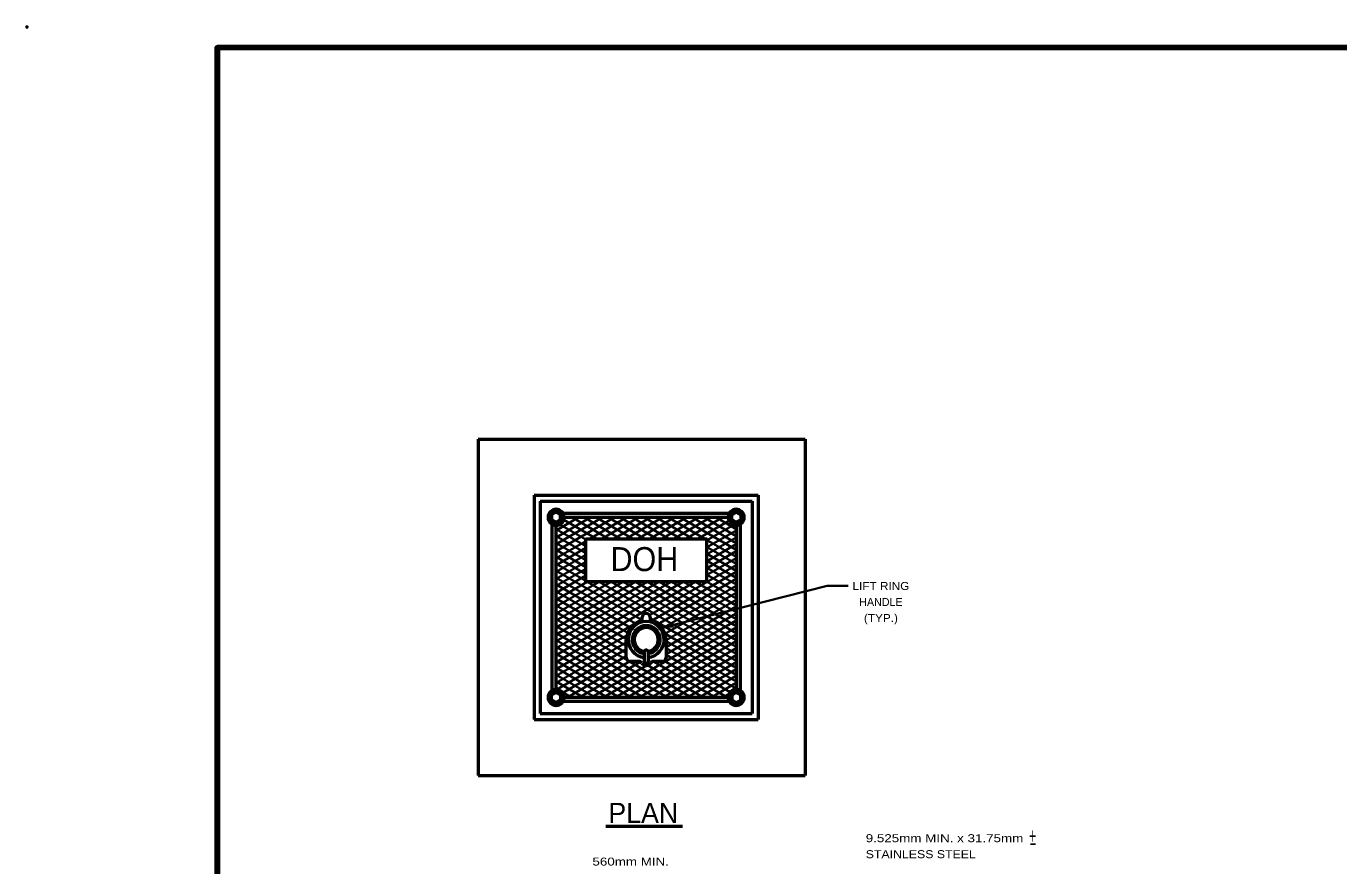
# Model space of a CAD drawing. Extents: x 442 to 1297, y -1132 to -588.
# Drawn here: x 441.8 to 835.5, y -839.5 to -587.7 of the extents above; entities that cross this region are included whole.
import ezdxf
from ezdxf.enums import TextEntityAlignment as Align

# ---------------------------------------------------------------- set-up
doc = ezdxf.new("R2010")
doc.units = 0
doc.header["$LTSCALE"] = 0.96
doc.header["$PDMODE"] = 32
doc.header["$PDSIZE"] = 0.48
doc.layers.add('1', color=7, linetype='Continuous', lineweight=35)

msp = doc.modelspace()

# ---------------------------------------------------------------- linework, layer by layer
at = {"layer": '1', "lineweight": 53}
for p, q in [((577.3476, -711.5929), (577.3476, -812.3929)), ((577.3476, -711.5929), (675.4476, -711.5929)), ((675.4476, -711.5929), (675.4476, -812.3929)), ((594.1476, -728.3929), (661.3476, -728.3929)), ((594.1476, -728.3929), (594.1476, -795.5929)), ((595.9476, -730.1929), (659.5476, -730.1929)), ((595.9476, -730.1929), (595.9476, -793.7929)), ((659.5476, -730.1929), (659.5476, -793.7929)), ((661.3476, -728.3929), (661.3476, -795.5929)), ((602.8261, -733.7929), (652.6691, -733.7929)), ((603.1476, -734.9929), (652.3476, -734.9929)), ((599.5476, -786.9144), (599.5476, -737.0714)), ((600.7476, -786.5929), (600.7476, -737.3929)), ((654.7476, -737.3929), (654.7476, -786.5929)), ((655.9476, -737.0714), (655.9476, -786.9144)), ((626.5476, -765.7284), (626.5476, -764.9459)), ((628.9476, -764.9459), (628.9476, -765.7284)), ((621.7926, -777.0434), (621.7926, -771.8587)), ((627.1497, -775.3059), (627.1497, -778.2434)), ((628.3455, -775.3059), (628.3455, -778.2434)), ((633.7029, -771.8012), (633.7029, -777.0434)), ((625.511, -778.2434), (622.9926, -778.2434)), ((632.5029, -778.2434), (629.9842, -778.2434)), ((652.3476, -790.1929), (602.8261, -790.1929)), ((652.3476, -788.9929), (603.1476, -788.9929)), ((595.9476, -793.7929), (659.5476, -793.7929)), ((594.1476, -795.5929), (661.3476, -795.5929)), ((577.3476, -812.3929), (675.4476, -812.3929)), ((615.6693, -827.601), (638.6356, -827.601))]:
    msp.add_line(p, q, dxfattribs=at)
at = {"layer": '1'}
for p, q in [((600.7476, -738.9178), (607.5458, -734.9929)), ((600.7476, -740.9963), (611.1458, -734.9929)), ((600.7476, -743.0748), (614.7458, -734.9929)), ((600.7476, -745.1532), (618.3458, -734.9929)), ((612.8985, -741.3983), (603.0297, -735.7005)), ((603.0762, -735.4949), (603.9458, -734.9929)), ((616.4985, -741.3983), (605.404, -734.9929)), ((620.0985, -741.3983), (609.004, -734.9929)), ((610.8513, -741.3983), (621.9458, -734.9929)), ((623.6985, -741.3983), (612.604, -734.9929)), ((614.4513, -741.3983), (625.5458, -734.9929)), ((627.2985, -741.3983), (616.204, -734.9929)), ((618.0513, -741.3983), (629.1458, -734.9929)), ((630.8985, -741.3983), (619.804, -734.9929)), ((621.6513, -741.3983), (632.7458, -734.9929)), ((634.4985, -741.3983), (623.404, -734.9929)), ((625.2513, -741.3983), (636.3458, -734.9929)), ((638.0985, -741.3983), (627.004, -734.9929)), ((628.8513, -741.3983), (639.9458, -734.9929)), ((641.6985, -741.3983), (630.604, -734.9929)), ((632.4513, -741.3983), (643.5458, -734.9929)), ((645.2985, -741.3983), (634.204, -734.9929)), ((636.0513, -741.3983), (647.1458, -734.9929)), ((654.7476, -744.7753), (637.804, -734.9929)), ((639.6513, -741.3983), (650.7458, -734.9929)), ((654.7476, -742.6968), (641.404, -734.9929)), ((643.2513, -741.3983), (652.5867, -736.0085)), ((654.7476, -740.6184), (645.004, -734.9929)), ((654.7476, -738.5399), (648.604, -734.9929)), ((652.358, -735.0818), (652.204, -734.9929)), ((609.6447, -743.6766), (600.7476, -738.5399)), ((609.6447, -741.5982), (601.8739, -737.1117)), ((645.8505, -741.9761), (654.0056, -737.2678)), ((645.8505, -744.0546), (654.7476, -738.9178)), ((609.6447, -745.7551), (600.7476, -740.6184)), ((600.7476, -747.2317), (609.6447, -742.0949)), ((609.6447, -747.8336), (600.7476, -742.6968)), ((645.8505, -746.133), (654.7476, -740.9963)), ((654.7476, -746.8538), (645.8505, -741.717)), ((645.8505, -748.2115), (654.7476, -743.0748)), ((654.7476, -748.9322), (645.8505, -743.7955)), ((600.7476, -749.3101), (609.6447, -744.1734)), ((609.6447, -749.912), (600.7476, -744.7753)), ((600.7476, -751.3886), (609.6447, -746.2519)), ((609.6447, -751.9905), (600.7476, -746.8538)), ((645.8505, -750.29), (654.7476, -745.1532)), ((654.7476, -751.0107), (645.8505, -745.8739)), ((645.8505, -752.3684), (654.7476, -747.2317)), ((654.7476, -753.0891), (645.8505, -747.9524)), ((600.7476, -753.4671), (609.6447, -748.3303)), ((609.6447, -754.069), (600.7476, -748.9322)), ((600.7476, -755.5455), (609.6447, -750.4088)), ((626.4986, -765.878), (600.7476, -751.0107)), ((628.7271, -764.3331), (654.7476, -749.3101)), ((629.322, -766.0681), (654.7476, -751.3886)), ((654.7476, -755.1676), (645.8505, -750.0309)), ((600.7476, -757.624), (609.6447, -752.4872)), ((624.5229, -766.8158), (600.7476, -753.0891)), ((600.7476, -759.7024), (610.0517, -754.3307)), ((600.7476, -761.7809), (613.6517, -754.3307)), ((600.7476, -763.8594), (617.2517, -754.3307)), ((600.7476, -765.9378), (620.8517, -754.3307)), ((600.7476, -768.0163), (624.4517, -754.3307)), ((600.7476, -770.0948), (628.0517, -754.3307)), ((600.7476, -772.1732), (631.6517, -754.3307)), ((600.7476, -774.2517), (635.2517, -754.3307)), ((600.7476, -776.3301), (638.8517, -754.3307)), ((600.7476, -778.4086), (642.4517, -754.3307)), ((623.1179, -768.0831), (600.7476, -755.1676)), ((627.0042, -764.0915), (610.0981, -754.3307)), ((654.7476, -778.0307), (613.6981, -754.3307)), ((654.7476, -775.9522), (617.2981, -754.3307)), ((654.7476, -773.8737), (620.8981, -754.3307)), ((654.7476, -771.7953), (624.4981, -754.3307)), ((654.7476, -769.7168), (628.0981, -754.3307)), ((631.2702, -767.0217), (654.7476, -753.4671)), ((654.7476, -767.6384), (631.6981, -754.3307)), ((632.4364, -768.1296), (682.0302, -755.499)), ((632.5763, -768.3461), (654.7476, -755.5455)), ((654.7476, -765.5599), (635.2981, -754.3307)), ((654.7476, -763.4814), (638.8981, -754.3307)), ((654.7476, -761.403), (642.4981, -754.3307)), ((654.7476, -757.2461), (645.8505, -752.1093)), ((654.7476, -759.3245), (645.8505, -754.1878)), ((688.3381, -755.499), (682.0302, -755.499)), ((622.2169, -769.6414), (600.7476, -757.2461)), ((621.8177, -771.4894), (600.7476, -759.3245)), ((633.3905, -769.9545), (654.7476, -757.624)), ((633.7029, -771.8526), (654.7476, -759.7024)), ((621.7926, -773.5533), (600.7476, -761.403)), ((621.7926, -775.6318), (600.7476, -763.4814)), ((633.7029, -773.9311), (654.7476, -761.7809)), ((622.2154, -777.9543), (600.7476, -765.5599)), ((600.7476, -780.4871), (626.5476, -765.5914)), ((637.7347, -788.9929), (600.7476, -767.6384)), ((614.8151, -788.9929), (654.7476, -765.9378)), ((654.7476, -780.1091), (628.9476, -765.2135)), ((633.7029, -776.0095), (654.7476, -763.8594)), ((634.1347, -788.9929), (600.7476, -769.7168)), ((600.7476, -782.5655), (622.0013, -770.2947)), ((618.4151, -788.9929), (654.7476, -768.0163)), ((622.0151, -788.9929), (654.7476, -770.0948)), ((654.7476, -782.1876), (633.3509, -769.8342)), ((630.5347, -788.9929), (600.7476, -771.7953)), ((600.7476, -784.644), (621.7926, -772.4936)), ((626.9347, -788.9929), (600.7476, -773.8737)), ((600.954, -786.6032), (621.7926, -774.5721)), ((625.6151, -788.9929), (654.7476, -772.1732)), ((629.2151, -788.9929), (654.7476, -774.2517)), ((654.7476, -784.266), (633.7029, -772.1159)), ((654.7476, -786.3445), (633.7029, -774.1943)), ((623.3347, -788.9929), (600.7476, -775.9522)), ((619.7347, -788.9929), (600.7476, -778.0307)), ((602.7227, -787.6606), (621.7926, -776.6506)), ((604.0151, -788.9929), (622.7173, -778.1952)), ((607.6151, -788.9929), (626.0107, -778.3722)), ((611.2151, -788.9929), (627.8655, -779.3798)), ((641.3347, -788.9929), (622.5956, -778.1739)), ((644.9347, -788.9929), (628.181, -779.3201)), ((629.0588, -778.6908), (629.7682, -778.2812)), ((648.5347, -788.9929), (629.9319, -778.2526)), ((632.8151, -788.9929), (654.7476, -776.3301)), ((652.1347, -788.9929), (633.1587, -778.0371)), ((652.9759, -787.4001), (633.7029, -776.2728)), ((636.4151, -788.9929), (654.7476, -778.4086)), ((616.1347, -788.9929), (600.7476, -780.1091)), ((612.5347, -788.9929), (600.7476, -782.1876)), ((640.0151, -788.9929), (654.7476, -780.4871)), ((643.6151, -788.9929), (654.7476, -782.5655)), ((608.9347, -788.9929), (600.7476, -784.266)), ((601.3349, -786.6836), (600.7476, -786.3445)), ((605.3347, -788.9929), (602.4899, -787.3504)), ((647.2151, -788.9929), (654.7476, -784.644)), ((650.8151, -788.9929), (652.5993, -787.9628))]:
    msp.add_line(p, q, dxfattribs=at)
at = {"layer": '1', "lineweight": 158}
msp.add_lwpolyline([(1290.7447, -594.0679), (499.0447, -594.1679), (499.1447, -1120.1679)], dxfattribs=at)
at = {"layer": '1', "lineweight": 53}
for points in [[(600.7476, -733.4929), (599.3968, -734.2411), (599.3968, -735.7411), (600.7476, -736.4929), (602.0968, -735.7411), (602.0969, -734.2411)], [(654.7476, -733.4929), (656.0984, -734.2411), (656.0984, -735.7411), (654.7476, -736.4929), (653.3984, -735.7411), (653.3983, -734.2411)], [(609.6447, -741.3983), (645.8505, -741.3983), (645.8505, -754.3307), (609.6447, -754.3307)], [(600.7476, -790.4929), (599.3968, -789.7447), (599.3968, -788.2447), (600.7476, -787.4929), (602.0968, -788.2447), (602.0969, -789.7447)], [(654.7476, -790.4929), (656.0984, -789.7447), (656.0984, -788.2447), (654.7476, -787.4929), (653.3984, -788.2447), (653.3983, -789.7447)]]:
    msp.add_lwpolyline(points, close=True, dxfattribs=at)
for centre in [(600.7476, -734.9929), (654.7476, -734.9929), (600.7476, -788.9929), (654.7476, -788.9929)]:
    msp.add_circle(centre, 1.8, dxfattribs=at)
for centre, radius, start, end in [((600.7476, -734.9929), 2.4, 0, 270), ((600.7476, -734.9929), 2.4, 270, 0), ((654.7476, -734.9929), 2.4, 270, 180), ((654.7476, -734.9929), 2.4, 180.14666, 268.87468), ((627.7476, -771.8012), 5.9553, 103.87448, 180.55336), ((627.7606, -771.6704), 5.4, 276.21818, 263.50424), ((627.7606, -771.6704), 4.2, 278.00514, 261.63652), ((626.2476, -765.7284), 0.3, 283.87448, 0), ((627.7476, -765.0136), 1.2019, 3.23002, 176.76998), ((629.2476, -765.7284), 0.3, 180, 256.12552), ((627.7476, -771.8012), 5.9553, 0, 76.12552), ((627.7606, -771.6704), 3.6, 279.14766, 260.4482), ((627.7476, -775.3565), 0.6, 4.83802, 175.16198), ((622.9926, -777.0434), 1.2, 180, 270), ((625.511, -779.4434), 1.2, 35.59881, 90), ((627.7476, -777.8422), 1.5507, 215.59881, 324.40119), ((627.7476, -778.1929), 0.6, 184.83802, 355.16198), ((629.9842, -779.4434), 1.2, 90, 144.40119), ((632.5029, -777.0434), 1.2, 270, 0), ((600.7476, -788.9929), 2.4, 90, 0), ((600.7476, -788.9929), 2.4, 0, 90), ((654.7476, -788.9929), 2.4, 180, 90), ((654.7476, -788.9929), 2.4, 90, 177.21613)]:
    msp.add_arc(centre, radius, start, end, dxfattribs=at)
at = {"layer": '1', "lineweight": 40}
for centre, major_axis, ratio, start_param, end_param in [((633.6235, -767.4851), (-2.0303, -0.7104), 0.122415, 0.89635335, 3.14159265), ((633.8021, -768.0438), (-2.0946, -0.3159), 0.07063, 3.14071475, 5.41810995)]:
    msp.add_ellipse(centre, major_axis=major_axis, ratio=ratio, start_param=start_param, end_param=end_param, dxfattribs=at)
at = {"layer": '1'}
msp.add_point((442.0447, -587.9679), dxfattribs=at)

# ---------------------------------------------------------------- texts
for s, height, width, p in [('DOH', 7.2, 0.95, (627.2124, -751.1237)), ('LIFT RING', 2.4, 1.1, (698.1608, -756.7845)), ('(TYP.)', 2.4, 1.1, (698.1607, -766.3845)), ('+', 4.8, 0.55, (743.6816, -832.9056)), ('560mm MIN.', 2.4, 1.25, (623.1082, -839.4362))]:
    msp.add_text(s, height=height, dxfattribs=dict(at, width=width)).set_placement(p, align=Align.CENTER)
for s, height, p in [('HANDLE', 2.4, (698.1607, -761.5845)), ('PLAN', 6, (626.8804, -826.6282)), ('-', 4.8, (743.7871, -834.8796))]:
    msp.add_text(s, height=height, dxfattribs=at).set_placement(p, align=Align.CENTER)
for s, width, p in [('9.525mm MIN. x 31.75mm', 1.25, (693.6064, -832.4146)), ('STAINLESS STEEL', 1.15, (693.6064, -837.2146))]:
    msp.add_text(s, height=2.4, dxfattribs=dict(at, width=width)).set_placement(p)

doc.saveas('drawing.dxf')
